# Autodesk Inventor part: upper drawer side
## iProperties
Created: 2005-05
Part Number: upper drawer side
Material: mdf
Document SubType Name: Modeling
Designer: a.campbell
Manufacturer: Standard
Standards Organization: Custom
length: 400
thickness: 12
width: 109
Author: a.campbell
Comments: machine to detail
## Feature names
1. Extrusion1
2. Extrusion2
